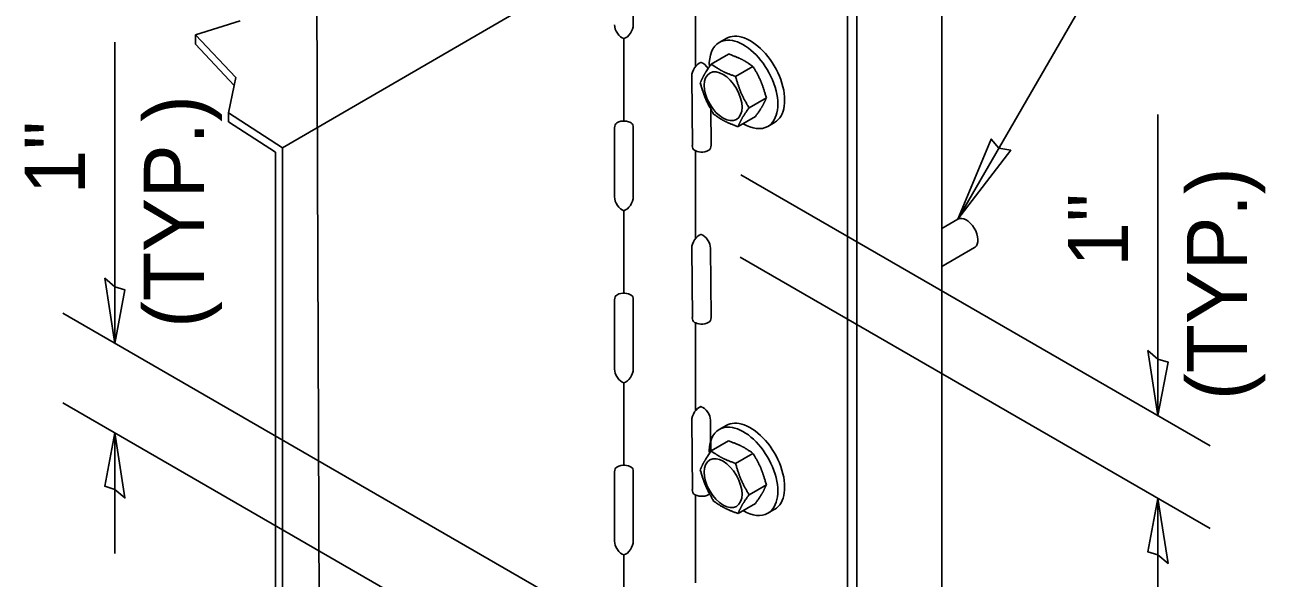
# Model space of a CAD drawing. Extents: x 99862 to 104211, y 98939 to 102076.
# Drawn here: x 101948 to 102277.6, y 100806.7 to 100953.7 of the extents above; entities that cross this region are included whole.
import ezdxf

# ---------------------------------------------------------------- set-up
doc = ezdxf.new("R2010")
doc.units = 0
for name, color, linetype in [('Level 1', 7, 'Continuous'), ('Level 11', 7, 'Continuous'), ('Level 12', 7, 'Continuous'), ('Level 15', 7, 'Continuous'), ('Level 18', 7, 'Continuous'), ('Level 19', 7, 'Continuous'), ('Level 20', 7, 'Continuous'), ('Level 21', 7, 'Continuous'), ('Level 5', 7, 'Continuous')]:
    doc.layers.add(name, color=color, linetype=linetype)

msp = doc.modelspace()

# ---------------------------------------------------------------- linework, layer by layer
at = {"layer": 'Level 1'}
for p, q in [((102026.72, 100657.67), (102025.26, 101043.13)), ((102126.24, 100984.83), (102016.49, 100921.01)), ((102126.24, 100942.66), (102126.24, 100966)), ((102005.27, 100954.82), (101993.39, 100951.12)), ((101993.39, 100951.12), (102004.07, 100939.72)), ((101993.39, 100948.59), (101993.39, 100951.12)), ((101993.39, 100948.59), (102003.64, 100937.65)), ((102003.64, 100937.65), (102002.11, 100930.32)), ((102004.07, 100939.72), (102003.64, 100937.65)), ((102002.11, 100930.32), (102002.11, 100927.98)), ((102002.11, 100930.32), (102016.49, 100921.01)), ((102002.11, 100927.98), (102014.58, 100919.9)), ((102016.49, 100921.01), (102016.49, 100534.05)), ((102126.24, 100896.93), (102126.24, 100920.28)), ((102014.58, 100919.9), (102014.58, 100651.67)), ((102126.24, 100851.21), (102126.24, 100874.55)), ((102126.24, 100805.49), (102126.24, 100828.83))]:
    msp.add_line(p, q, dxfattribs=at)
at = {"layer": 'Level 11'}
for points in [[(102122.89, 100602.15), (102166.62, 100576.89), (102169.1, 100578.32), (102169.1, 100970.44)], [(102169.1, 100970.44), (102166.62, 100969.01), (102166.62, 100576.89)]]:
    msp.add_lwpolyline(points, dxfattribs=at)
at = {"layer": 'Level 12'}
for p, q in [((102109.71, 100972.11), (102109.71, 100953.74)), ((102127.69, 100943.73), (102127.71, 100943.73)), ((102125.4, 100921.68), (102125.24, 100940.05)), ((102130.29, 100931.4), (102130.37, 100921.73)), ((102104.73, 100908.01), (102104.74, 100926.39)), ((102109.71, 100926.38), (102109.71, 100908.01)), ((102125.4, 100875.96), (102125.24, 100894.33)), ((102130.22, 100894.37), (102130.37, 100876)), ((102104.73, 100862.29), (102104.74, 100880.66)), ((102109.71, 100880.66), (102109.71, 100862.29)), ((102127.69, 100852.29), (102127.71, 100852.29)), ((102125.4, 100830.24), (102125.24, 100848.61)), ((102130.22, 100848.65), (102130.29, 100840.32)), ((102104.73, 100816.57), (102104.74, 100834.94)), ((102109.71, 100834.94), (102109.71, 100816.57))]:
    msp.add_line(p, q, dxfattribs=at)
for centre, major_axis, start_param, end_param in [((102106.72, 100952.59), (-1.41, 2.44), 0.785398, 2.604966), ((102107.72, 100952.59), (-1.41, -2.44), 0.536627, 2.356194), ((102127.22, 100941.22), (1.39, 2.45), 0.536627, 2.356194), ((102128.22, 100941.23), (1.43, -2.42), 1.58521, 2.604966), ((102106.73, 100925.24), (-1.41, 2.44), 6.283185, 7.068583), ((102107.72, 100925.24), (-1.41, -2.44), 2.356194, 3.141593), ((102127.38, 100922.85), (1.39, 2.45), 2.356194, 3.141593), ((102128.38, 100922.86), (1.43, -2.42), 6.283185, 7.068583), ((102106.72, 100906.87), (-1.41, 2.44), 0.785398, 2.604966), ((102107.72, 100906.87), (-1.41, -2.44), 0.536627, 2.356194), ((102127.22, 100895.5), (1.39, 2.45), 0.536627, 2.356194), ((102128.22, 100895.5), (1.43, -2.42), 0.785398, 2.604966), ((102106.73, 100879.51), (-1.41, 2.44), 6.283185, 7.068583), ((102107.72, 100879.51), (-1.41, -2.44), 2.356194, 3.141593), ((102127.38, 100877.13), (1.39, 2.45), 2.356194, 3.141593), ((102128.38, 100877.13), (1.43, -2.42), 6.283185, 7.068583), ((102106.72, 100861.14), (-1.41, 2.44), 0.785398, 2.604966), ((102107.72, 100861.14), (-1.41, -2.44), 0.536627, 2.356194), ((102127.22, 100849.77), (1.39, 2.45), 0.536627, 2.356194), ((102128.22, 100849.78), (1.43, -2.42), 0.785398, 2.604966), ((102106.73, 100833.79), (-1.41, 2.44), 6.283185, 7.068583), ((102107.72, 100833.79), (-1.41, -2.44), 2.356194, 3.141593), ((102127.38, 100831.4), (1.39, 2.45), 2.356194, 3.141593), ((102128.38, 100831.41), (1.43, -2.42), 6.283185, 6.443177), ((102106.72, 100815.42), (-1.41, 2.44), 0.785398, 2.604966), ((102107.72, 100815.42), (-1.41, -2.44), 0.536627, 2.356194)]:
    msp.add_ellipse(centre, major_axis=major_axis, ratio=0.57735, start_param=start_param, end_param=end_param, dxfattribs=at)
for points in [[(102105.32, 100927.67), (102106.09, 100928.12), (102107.49, 100928.33), (102108.75, 100927.89), (102109.13, 100927.67)], [(102129.8, 100920.43), (102129.04, 100919.98), (102127.65, 100919.76), (102126.37, 100920.19), (102126, 100920.4)], [(102105.32, 100881.95), (102106.09, 100882.39), (102107.49, 100882.61), (102108.75, 100882.17), (102109.13, 100881.95)], [(102129.8, 100874.71), (102129.04, 100874.26), (102127.65, 100874.03), (102126.37, 100874.46), (102126, 100874.68)], [(102105.32, 100836.23), (102106.09, 100836.67), (102107.49, 100836.89), (102108.75, 100836.44), (102109.13, 100836.22)], [(102129.8, 100828.99), (102129.04, 100828.54), (102127.65, 100828.31), (102126.37, 100828.74), (102126, 100828.95)]]:
    msp.add_open_spline(points, degree=3, dxfattribs=at)
at = {"layer": 'Level 15'}
for p, q in [((102196, 100902.11), (102240.66, 100979.47)), ((101971.95, 100869.11), (101971.95, 100949.11)), ((102249.15, 100849.92), (102249.15, 100929.92)), ((102138.3, 100913.92), (102263, 100841.92)), ((102138.1, 100892.01), (102263, 100819.9)), ((101958.09, 100877.11), (102096.85, 100797)), ((101958.08, 100853.3), (102096.84, 100773.19)), ((101971.93, 100845.3), (101971.93, 100813.3)), ((102249.15, 100827.9), (102249.15, 100795.9))]:
    msp.add_line(p, q, dxfattribs=at)
for points in [[(102196, 100902.11), (102210, 100920.39), (102206.89, 100920.97), (102204.83, 100923.37)], [(101971.95, 100869.11), (101974.62, 100883.3), (101971.95, 100884.11), (101969.27, 100886.39)], [(102249.15, 100849.92), (102251.82, 100864.11), (102249.15, 100864.92), (102246.47, 100867.2)], [(101971.93, 100845.3), (101974.6, 100828.03), (101971.93, 100830.3), (101969.26, 100831.12)], [(102249.15, 100827.9), (102251.82, 100810.62), (102249.15, 100812.9), (102246.48, 100813.71)]]:
    msp.add_lwpolyline(points, close=True, dxfattribs=at)
for points in [[(102166.62, 100812.67), (102166.62, 100915.47)], [(102166.62, 100709.87), (102166.62, 100812.67)]]:
    msp.add_lwpolyline(points, dxfattribs=at)
at = {"layer": 'Level 18'}
for points in [[(102107.23, 100950.08), (102107.23, 100928.17)], [(102107.23, 100904.36), (102107.23, 100882.44)], [(102107.23, 100858.63), (102107.23, 100836.72)], [(102107.23, 100812.91), (102107.23, 100791)]]:
    msp.add_lwpolyline(points, dxfattribs=at)
at = {"layer": 'Level 19'}
for p, q in [((102134.4, 100950.1), (102132.57, 100949.05)), ((102135.05, 100945.98), (102130.43, 100943.31)), ((102136.9, 100940), (102141.52, 100942.67)), ((102140.46, 100931.68), (102145.08, 100934.35)), ((102142.16, 100929.35), (102137.54, 100926.68)), ((102145.44, 100926.75), (102147.27, 100927.81)), ((102196, 100902.11), (102191.72, 100899.64)), ((102191.72, 100889.54), (102200.38, 100894.53)), ((102200.41, 100894.55), (102200.53, 100894.63)), ((102134.4, 100847.3), (102132.57, 100846.25)), ((102135.05, 100843.18), (102130.43, 100840.51)), ((102136.9, 100837.2), (102141.52, 100839.87)), ((102140.46, 100828.88), (102145.08, 100831.55)), ((102142.16, 100826.55), (102137.54, 100823.88)), ((102145.44, 100823.95), (102147.27, 100825.01))]:
    msp.add_line(p, q, dxfattribs=at)
for centre, major_axis, start_param, end_param in [((102139.01, 100937.9), (6.44, -11.15), 2.536598, 3.141593), ((102140.83, 100938.95), (6.44, -11.15), 2.536598, 3.141593), ((102140.83, 100938.95), (6.44, -11.15), 6.283185, 8.819783), ((102139.01, 100937.9), (6.44, -11.15), 3.141593, 3.981212), ((102139.01, 100937.9), (6.44, -11.15), 6.283185, 8.819783), ((102139.01, 100937.9), (6.44, -11.15), 5.484453, 6.283185), ((102198.19, 100898.32), (2.19, -3.79), 0.072191, 3.141593), ((102198.19, 100898.32), (2.19, -3.79), 6.283185, 6.355376), ((102140.83, 100836.15), (6.44, -11.15), 2.536598, 3.141593), ((102139.01, 100835.1), (6.44, -11.15), 3.141593, 3.981212), ((102139.01, 100835.1), (6.44, -11.15), 2.536598, 3.141593), ((102139.01, 100835.1), (6.44, -11.15), 6.283185, 8.819783), ((102140.83, 100836.15), (6.44, -11.15), 6.283185, 8.819783), ((102139.01, 100835.1), (6.44, -11.15), 5.484453, 6.283185)]:
    msp.add_ellipse(centre, major_axis=major_axis, ratio=0.57735, start_param=start_param, end_param=end_param, dxfattribs=at)
for centre in [(102133.58, 100934.76), (102133.58, 100831.96)]:
    msp.add_ellipse(centre, major_axis=(3.55, -6.16), ratio=0.57735, dxfattribs=at)
for points in [[(102130.43, 100943.31), (102129.12, 100941.46), (102128.16, 100939.79), (102127.51, 100938.31)], [(102136.9, 100940), (102134.41, 100940.91), (102132.26, 100942.02), (102130.43, 100943.31)], [(102141.52, 100942.67), (102139.7, 100943.96), (102137.53, 100945.06), (102135.05, 100945.98)], [(102140.46, 100931.68), (102138.97, 100934.26), (102137.74, 100937.04), (102136.9, 100940)], [(102145.08, 100934.35), (102144.21, 100937.28), (102143.04, 100940.11), (102141.52, 100942.67)], [(102127.51, 100938.31), (102128.34, 100935.36), (102129.58, 100932.58), (102131.06, 100930)], [(102142.16, 100929.35), (102143.46, 100931.21), (102144.43, 100932.87), (102145.08, 100934.35)], [(102131.06, 100930), (102132.89, 100928.7), (102135.05, 100927.6), (102137.54, 100926.68)], [(102137.54, 100926.68), (102138.18, 100928.16), (102139.16, 100929.83), (102140.46, 100931.68)], [(102141.52, 100839.87), (102139.7, 100841.16), (102137.53, 100842.26), (102135.05, 100843.18)], [(102130.43, 100840.51), (102129.12, 100838.66), (102128.16, 100836.99), (102127.51, 100835.51)], [(102136.9, 100837.2), (102134.41, 100838.11), (102132.26, 100839.22), (102130.43, 100840.51)], [(102145.08, 100831.55), (102144.21, 100834.48), (102143.04, 100837.31), (102141.52, 100839.87)], [(102127.51, 100835.51), (102128.34, 100832.56), (102129.58, 100829.78), (102131.06, 100827.2)], [(102140.46, 100828.88), (102138.97, 100831.46), (102137.74, 100834.24), (102136.9, 100837.2)], [(102142.16, 100826.55), (102143.46, 100828.41), (102144.43, 100830.07), (102145.08, 100831.55)], [(102137.54, 100823.88), (102138.18, 100825.36), (102139.16, 100827.03), (102140.46, 100828.88)], [(102131.06, 100827.2), (102132.89, 100825.9), (102135.05, 100824.8), (102137.54, 100823.88)]]:
    msp.add_open_spline(points, degree=2, dxfattribs=at)
at = {"layer": 'Level 21'}
for p, q in [((102109.71, 100953.74), (102109.71, 100972.11)), ((102107.21, 100950.08), (102107.23, 100950.08)), ((102127.71, 100943.73), (102127.69, 100943.73)), ((102125.24, 100940.05), (102125.4, 100921.68)), ((102130.37, 100921.73), (102130.29, 100931.4)), ((102104.74, 100926.39), (102104.73, 100908.01)), ((102104.74, 100926.39), (102104.74, 100926.39)), ((102109.71, 100908.01), (102109.71, 100926.38)), ((102107.21, 100904.36), (102107.23, 100904.36)), ((102127.71, 100898.01), (102127.69, 100898.01)), ((102125.24, 100894.33), (102125.4, 100875.96)), ((102130.37, 100876), (102130.22, 100894.37)), ((102104.74, 100880.66), (102104.73, 100862.29)), ((102104.74, 100880.66), (102104.74, 100880.66)), ((102109.71, 100862.29), (102109.71, 100880.66)), ((102130.37, 100876), (102130.37, 100876)), ((102107.21, 100858.63), (102107.23, 100858.63)), ((102127.71, 100852.29), (102127.69, 100852.29)), ((102125.24, 100848.61), (102125.4, 100830.24)), ((102130.26, 100843.06), (102130.22, 100848.65)), ((102104.74, 100834.94), (102104.73, 100816.57)), ((102104.74, 100834.94), (102104.74, 100834.94)), ((102109.71, 100816.57), (102109.71, 100834.94)), ((102107.21, 100812.91), (102107.23, 100812.91))]:
    msp.add_line(p, q, dxfattribs=at)
for centre, major_axis, start_param, end_param in [((102106.72, 100952.59), (-1.41, 2.44), 0.785398, 2.604966), ((102107.72, 100952.59), (-1.41, -2.44), 0.536627, 2.356194), ((102127.22, 100941.22), (1.39, 2.45), 0.536627, 2.356194), ((102128.22, 100941.23), (1.43, -2.42), 1.58521, 2.604966), ((102106.73, 100925.24), (-1.41, 2.44), 6.283185, 7.068545), ((102107.72, 100925.24), (-1.41, -2.44), 2.356194, 3.141593), ((102127.38, 100922.85), (1.39, 2.45), 2.356194, 3.141593), ((102128.38, 100922.86), (1.43, -2.42), 6.283185, 7.068583), ((102106.72, 100906.87), (-1.41, 2.44), 0.785398, 2.604966), ((102107.72, 100906.87), (-1.41, -2.44), 0.536627, 2.356194), ((102127.22, 100895.5), (1.39, 2.45), 0.536627, 2.356194), ((102128.22, 100895.5), (1.43, -2.42), 0.785398, 2.604966), ((102106.73, 100879.51), (-1.41, 2.44), 6.283185, 7.068545), ((102107.72, 100879.51), (-1.41, -2.44), 2.356194, 3.141593), ((102127.38, 100877.13), (1.39, 2.45), 2.356194, 3.141593), ((102128.38, 100877.13), (1.43, -2.42), 6.283185, 7.068545), ((102106.72, 100861.14), (-1.41, 2.44), 0.785398, 2.604966), ((102107.72, 100861.14), (-1.41, -2.44), 0.536627, 2.356194), ((102127.22, 100849.77), (1.39, 2.45), 0.536627, 2.356194), ((102128.22, 100849.78), (1.43, -2.42), 0.785398, 2.604966), ((102139.01, 100835.1), (6.44, -11.15), 3.646052, 3.981212), ((102106.73, 100833.79), (-1.41, 2.44), 6.283185, 7.068545), ((102107.72, 100833.79), (-1.41, -2.44), 2.356194, 3.141593), ((102127.38, 100831.4), (1.39, 2.45), 2.356194, 3.141593), ((102128.38, 100831.41), (1.43, -2.42), 6.283185, 6.443177), ((102106.72, 100815.42), (-1.41, 2.44), 0.785398, 2.604966), ((102107.72, 100815.42), (-1.41, -2.44), 0.536627, 2.356194)]:
    msp.add_ellipse(centre, major_axis=major_axis, ratio=0.57735, start_param=start_param, end_param=end_param, dxfattribs=at)
for points, degree in [([(102127.51, 100938.31), (102128.01, 100939.46), (102128.7, 100940.72), (102129.6, 100942.09)], 2), ([(102130.29, 100931.4), (102129.15, 100933.58), (102128.19, 100935.89), (102127.51, 100938.31)], 2), ([(102109.13, 100927.67), (102108.75, 100927.89), (102107.49, 100928.33), (102106.09, 100928.12), (102105.32, 100927.67)], 3), ([(102126, 100920.4), (102126.37, 100920.19), (102127.65, 100919.76), (102129.04, 100919.98), (102129.8, 100920.43)], 3), ([(102109.13, 100881.95), (102108.75, 100882.17), (102107.49, 100882.61), (102106.09, 100882.39), (102105.32, 100881.95)], 3), ([(102126, 100874.68), (102126.37, 100874.46), (102127.65, 100874.03), (102129.04, 100874.26), (102129.8, 100874.71)], 3), ([(102127.51, 100835.51), (102128.07, 100836.8), (102128.87, 100838.21), (102129.92, 100839.78)], 2), ([(102109.13, 100836.22), (102108.75, 100836.44), (102107.49, 100836.89), (102106.09, 100836.67), (102105.32, 100836.23)], 3), ([(102130.01, 100829.15), (102128.99, 100831.16), (102128.13, 100833.29), (102127.51, 100835.51)], 2), ([(102126, 100828.95), (102126.37, 100828.74), (102127.65, 100828.31), (102129.04, 100828.54), (102129.8, 100828.99)], 3)]:
    msp.add_open_spline(points, degree=degree, dxfattribs=at)
at = {"layer": 'Level 5'}
msp.add_line((102191.72, 101017.39), (102191.72, 100579.55), dxfattribs=at)

# ---------------------------------------------------------------- texts
at = {"layer": 'Level 20'}
for s, p in [('(TYP.)', (101995.63, 100873.23)), ('1"', (101964, 100908.66)), ('(TYP.)', (102272.83, 100854.05)), ('1"', (102241.2, 100889.47))]:
    msp.add_text(s, height=16, rotation=90.0001, dxfattribs=at).set_placement(p)

doc.saveas('drawing.dxf')
